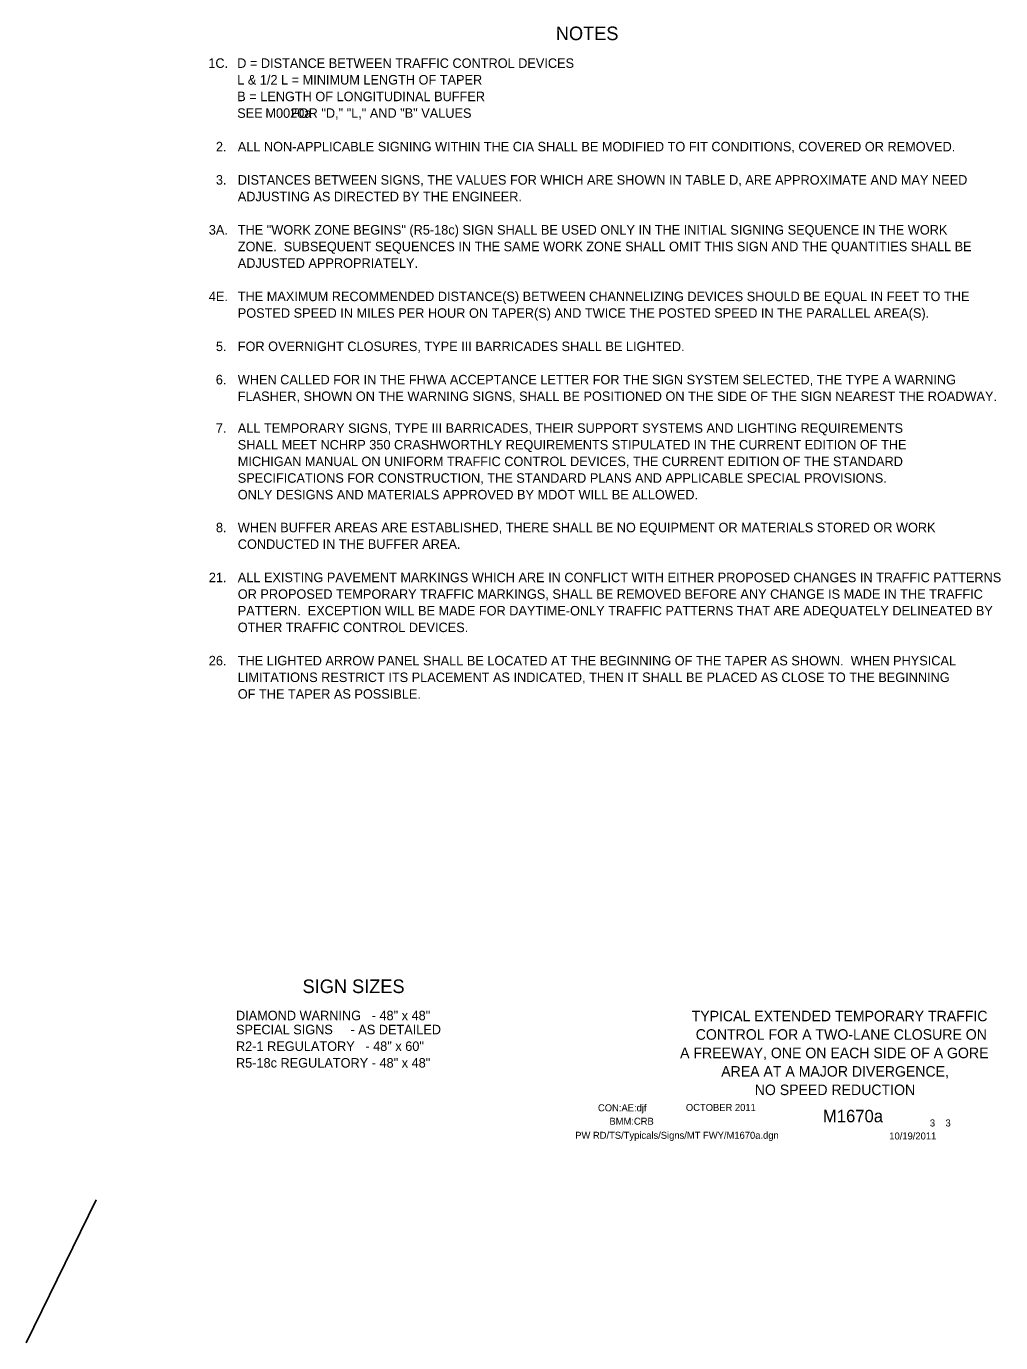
# Model space of a CAD drawing. Extents: x 16715 to 19504, y 7040 to 8495.
# Drawn here: x 18644 to 19504, y 7040 to 8203 of the extents above; entities that cross this region are included whole.
import ezdxf

# ---------------------------------------------------------------- set-up
doc = ezdxf.new("R2010")
doc.units = 0
for name, color, linetype in [('BORDER', 7, 'Continuous'), ('BORDER_SIGNAL_WO', 7, 'Continuous'), ('TYPICAL_TEXT_DIMEN_PR', 7, 'Continuous')]:
    doc.layers.add(name, color=color, linetype=linetype)

msp = doc.modelspace()

# ---------------------------------------------------------------- linework, layer by layer
at = {"layer": 'BORDER'}
msp.add_line((18958.7, 7361.1), (18958.7, 7361.1), dxfattribs=at)
at = {"layer": 'TYPICAL_TEXT_DIMEN_PR'}
msp.add_line((18705.8, 7166.2), (18644, 7039.9), dxfattribs=at)

# ---------------------------------------------------------------- texts
at = {"layer": 'BORDER'}
for s, p in [('TYPICAL EXTENDED TEMPORARY TRAFFIC', (19231.4, 7323.8)), ('CONTROL FOR A TWO-LANE CLOSURE ON', (19235, 7307.5)), ('A FREEWAY, ONE ON EACH SIDE OF A GORE', (19221.2, 7291.2)), ('AREA AT A MAJOR DIVERGENCE,', (19257.5, 7274.9)), ('NO SPEED REDUCTION', (19287.1, 7258.6))]:
    msp.add_text(s, height=9.3, dxfattribs=at).set_placement(p)
at = {"layer": 'BORDER_SIGNAL_WO'}
for s, height, p in [('CON:AE:djf  ', 6.2, (19148.7, 7244.3)), ('    OCTOBER 2011    ', 6.2, (19217.1, 7244.6)), ('    M1670a   ', 11, (19330.9, 7234.6)), ('BMM:CRB   ', 6.2, (19158.8, 7232.4)), (' 3    3 ', 6.2, (19439.4, 7230.9)), ('PW RD/TS/Typicals/Signs/MT FWY/M1670a.dgn      ', 6.2, (19128.6, 7220)), ('10/19/2011    ', 6.2, (19405.9, 7219.4))]:
    msp.add_text(s, height=height, dxfattribs=at).set_placement(p)
at = {"layer": 'TYPICAL_TEXT_DIMEN_PR'}
for s, height, p in [('NOTES', 12, (19111.5, 8190.3)), ('1C.', 8.4, (18804.7, 8165.8)), ('D = DISTANCE BETWEEN TRAFFIC CONTROL DEVICES', 8.4, (18830.2, 8165.8)), ('L & 1/2 L = MINIMUM LENGTH OF TAPER', 8.4, (18830.2, 8151.1)), ('B = LENGTH OF LONGITUDINAL BUFFER', 8.4, (18830.2, 8136.4)), ('SEE        FOR "D," "L," AND "B" VALUES', 8.4, (18830.2, 8121.7)), ('M0020a', 8.4, (18855.1, 8121.7)), ('2.', 8.4, (18811.4, 8092.1)), ('ALL NON-APPLICABLE SIGNING WITHIN THE CIA SHALL BE MODIFIED TO FIT CONDITIONS, COVERED OR REMOVED.', 8.4, (18830.7, 8092.1)), ('3.', 8.4, (18811.4, 8062.7)), ('DISTANCES BETWEEN SIGNS, THE VALUES FOR WHICH ARE SHOWN IN TABLE D, ARE APPROXIMATE AND MAY NEED', 8.4, (18830.7, 8062.7)), ('ADJUSTING AS DIRECTED BY THE ENGINEER.', 8.4, (18830.7, 8048)), ('3A.', 8.4, (18805.1, 8018.6)), ('THE "WORK ZONE BEGINS" (R5-18c) SIGN SHALL BE USED ONLY IN THE INITIAL SIGNING SEQUENCE IN THE WORK', 8.4, (18830.7, 8018.6)), ('ZONE.  SUBSEQUENT SEQUENCES IN THE SAME WORK ZONE SHALL OMIT THIS SIGN AND THE QUANTITIES SHALL BE', 8.4, (18830.7, 8003.9)), ('ADJUSTED APPROPRIATELY.', 8.4, (18830.7, 7989.2)), ('4E.', 8.4, (18805.1, 7959.8)), ('THE MAXIMUM RECOMMENDED DISTANCE(S) BETWEEN CHANNELIZING DEVICES SHOULD BE EQUAL IN FEET TO THE', 8.4, (18830.7, 7959.8)), ('POSTED SPEED IN MILES PER HOUR ON TAPER(S) AND TWICE THE POSTED SPEED IN THE PARALLEL AREA(S).', 8.4, (18830.7, 7945.1)), ('5.', 8.4, (18811.4, 7915.7)), ('FOR OVERNIGHT CLOSURES, TYPE III BARRICADES SHALL BE LIGHTED.', 8.4, (18830.7, 7915.7)), ('6.', 8.4, (18811.3, 7886.3)), ('WHEN CALLED FOR IN THE FHWA ACCEPTANCE LETTER FOR THE SIGN SYSTEM SELECTED, THE TYPE A WARNING ', 8.4, (18830.7, 7886.3)), ('FLASHER, SHOWN ON THE WARNING SIGNS, SHALL BE POSITIONED ON THE SIDE OF THE SIGN NEAREST THE ROADWAY.', 8.4, (18830.7, 7871.6)), ('7.', 8.4, (18811.3, 7843.5)), ('ALL TEMPORARY SIGNS, TYPE III BARRICADES, THEIR SUPPORT SYSTEMS AND LIGHTING REQUIREMENTS', 8.4, (18830.7, 7843.5)), ('SHALL MEET NCHRP 350 CRASHWORTHLY REQUIREMENTS STIPULATED IN THE CURRENT EDITION OF THE', 8.4, (18830.7, 7828.8)), ('MICHIGAN MANUAL ON UNIFORM TRAFFIC CONTROL DEVICES, THE CURRENT EDITION OF THE STANDARD', 8.4, (18830.7, 7814.1)), ('SPECIFICATIONS FOR CONSTRUCTION, THE STANDARD PLANS AND APPLICABLE SPECIAL PROVISIONS.', 8.4, (18830.7, 7799.4)), ('ONLY DESIGNS AND MATERIALS APPROVED BY MDOT WILL BE ALLOWED.', 8.4, (18830.7, 7784.7)), ('8.', 8.4, (18811.4, 7755.7)), ('WHEN BUFFER AREAS ARE ESTABLISHED, THERE SHALL BE NO EQUIPMENT OR MATERIALS STORED OR WORK     ', 8.4, (18830.7, 7755.7)), ('CONDUCTED IN THE BUFFER AREA.', 8.4, (18830.7, 7741)), ('21.', 8.4, (18805.1, 7711.6)), ('ALL EXISTING PAVEMENT MARKINGS WHICH ARE IN CONFLICT WITH EITHER PROPOSED CHANGES IN TRAFFIC PATTERNS', 8.4, (18830.7, 7711.6)), ('OR PROPOSED TEMPORARY TRAFFIC MARKINGS, SHALL BE REMOVED BEFORE ANY CHANGE IS MADE IN THE TRAFFIC', 8.4, (18830.7, 7696.9)), ('PATTERN.  EXCEPTION WILL BE MADE FOR DAYTIME-ONLY TRAFFIC PATTERNS THAT ARE ADEQUATELY DELINEATED BY', 8.4, (18830.7, 7682.2)), ('OTHER TRAFFIC CONTROL DEVICES.', 8.4, (18830.7, 7667.5)), ('26.', 8.4, (18805.1, 7638.1)), ('THE LIGHTED ARROW PANEL SHALL BE LOCATED AT THE BEGINNING OF THE TAPER AS SHOWN.  WHEN PHYSICAL', 8.4, (18830.7, 7638.1)), ('LIMITATIONS RESTRICT ITS PLACEMENT AS INDICATED, THEN IT SHALL BE PLACED AS CLOSE TO THE BEGINNING', 8.4, (18830.7, 7623.4)), ('OF THE TAPER AS POSSIBLE.', 8.4, (18830.7, 7608.7)), ('SIGN SIZES', 12, (18887.9, 7348.7)), ('DIAMOND WARNING   - 48" x 48"', 8.4, (18829.1, 7324.7)), ('SPECIAL SIGNS     - AS DETAILED', 8.4, (18829.1, 7312.3)), ('R2-1 REGULATORY   - 48" x 60"', 8.4, (18829.1, 7297.6)), ('R5-18c REGULATORY - 48" x 48"', 8.4, (18829.1, 7282.9))]:
    msp.add_text(s, height=height, dxfattribs=at).set_placement(p)

doc.saveas('drawing.dxf')
